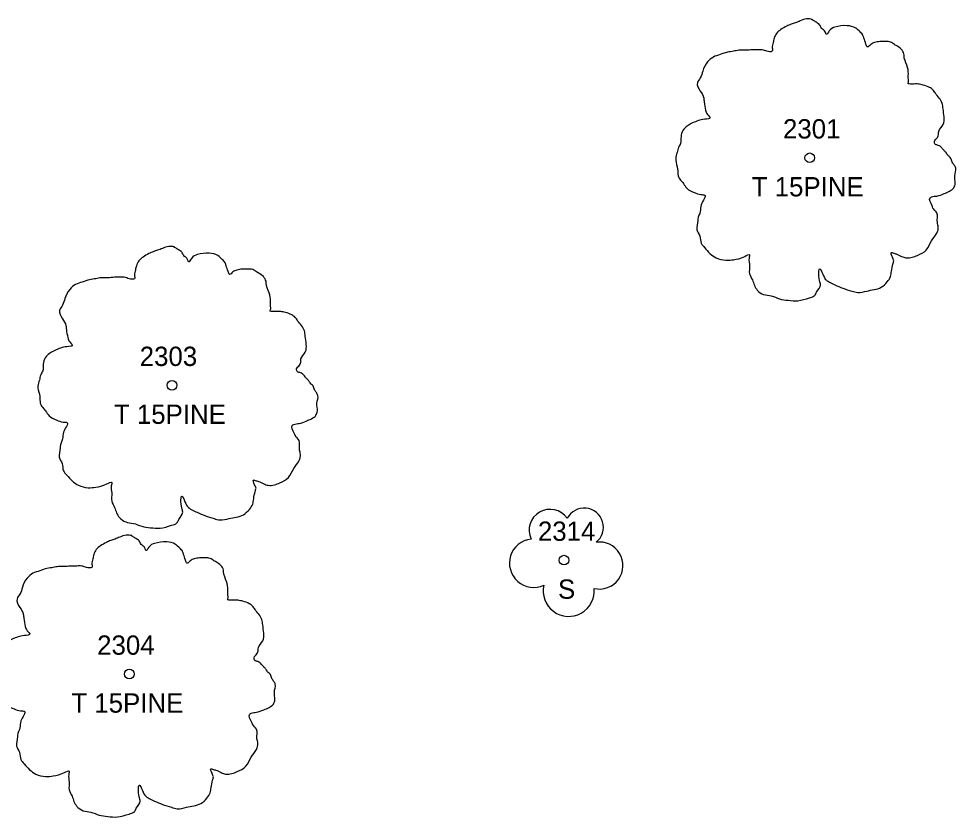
# Model space of a CAD drawing. Extents: x 2266664 to 2272542, y 716533 to 724777.
# Drawn here: x 2271573.66 to 2271622.19, y 723538.94 to 723580.3 of the extents above; entities that cross this region are included whole.
import ezdxf

# ---------------------------------------------------------------- set-up
doc = ezdxf.new("R2010")
doc.units = 0
doc.layers.add('RD_EX_VEG', color=7, linetype='Continuous')
doc.layers.add('RD_EX_VEG_txCode', color=7, linetype='Continuous')

msp = doc.modelspace()

# ---------------------------------------------------------------- linework, layer by layer
at = {"layer": 'RD_EX_VEG'}
for centre, radius in [((2271614.608, 723573.096), 0.25), ((2271614.595, 723573.077), 0.0001), ((2271581.591, 723561.315), 0.25), ((2271581.579, 723561.296), 0.0001), ((2271601.883, 723552.26), 0.25), ((2271579.387, 723546.361), 0.25), ((2271579.375, 723546.342), 0.0001)]:
    msp.add_circle(centre, radius, dxfattribs=at)
for centre, radius, start, end in [((2271601.162, 723553.807), 1.084, 34.9763, 204.756), ((2271602.928, 723553.962), 0.995, 308.7626, 152.0467), ((2271600.319, 723552.105), 1.257, 96.4518, 294.734), ((2271603.722, 723551.981), 1.218, 256.5667, 98.1046), ((2271602.128, 723550.664), 1.318, 166.8827, 5.7589)]:
    msp.add_arc(centre, radius, start, end, dxfattribs=at)
for points in [[(2271614.74, 723580.263), (2271614.44, 723580.288), (2271614.115, 723580.188), (2271613.865, 723580.088), (2271613.64, 723580.013), (2271613.415, 723579.913), (2271613.115, 723579.738), (2271612.89, 723579.538), (2271612.765, 723579.288), (2271612.715, 723579.063), (2271612.666, 723578.789), (2271612.666, 723578.614), (2271612.541, 723578.589), (2271612.391, 723578.614), (2271612.141, 723578.689), (2271611.891, 723578.689), (2271611.641, 723578.689), (2271611.291, 723578.664), (2271610.941, 723578.664), (2271610.666, 723578.614), (2271610.342, 723578.564), (2271609.967, 723578.439), (2271609.617, 723578.314), (2271609.317, 723578.064), (2271609.067, 723577.589), (2271608.942, 723577.239), (2271608.792, 723576.989), (2271608.942, 723576.54), (2271609.117, 723576.19), (2271609.142, 723575.99), (2271609.217, 723575.565), (2271609.317, 723575.34), (2271609.442, 723575.14), (2271609.367, 723575.115), (2271608.992, 723575.065), (2271608.692, 723574.965), (2271608.267, 723574.74), (2271608.043, 723574.515), (2271607.943, 723574.191), (2271607.918, 723573.841), (2271607.818, 723573.641), (2271607.743, 723573.366), (2271607.718, 723573.291), (2271607.668, 723572.966), (2271607.768, 723572.516), (2271607.793, 723572.166), (2271607.918, 723571.942), (2271608.068, 723571.767), (2271608.242, 723571.517), (2271608.642, 723571.292), (2271608.967, 723571.192), (2271609.167, 723571.167), (2271608.992, 723570.667), (2271608.942, 723570.317), (2271608.817, 723569.917), (2271608.817, 723569.843), (2271608.767, 723569.368), (2271608.917, 723569.043), (2271608.992, 723568.668), (2271609.167, 723568.443), (2271609.442, 723568.143), (2271609.767, 723567.918), (2271610.267, 723567.793), (2271610.666, 723567.818), (2271611.241, 723567.993), (2271611.491, 723568.068), (2271611.466, 723567.893), (2271611.491, 723567.518), (2271611.491, 723567.094), (2271611.641, 723566.769), (2271611.741, 723566.494), (2271611.891, 723566.244), (2271612.216, 723566.019), (2271612.616, 723565.944), (2271613.04, 723565.794), (2271613.49, 723565.719), (2271613.99, 723565.694), (2271614.59, 723565.844), (2271614.865, 723565.969), (2271614.965, 723566.144), (2271615.164, 723566.519), (2271615.114, 723566.744), (2271615.139, 723567.344), (2271615.239, 723567.169), (2271615.414, 723566.819), (2271615.914, 723566.519), (2271616.314, 723566.344), (2271616.789, 723566.194), (2271617.089, 723566.119), (2271617.563, 723566.194), (2271617.938, 723566.269), (2271618.313, 723566.394), (2271618.613, 723566.669), (2271618.788, 723566.944), (2271618.838, 723567.219), (2271618.913, 723567.593), (2271618.963, 723567.768)], [(2271618.963, 723567.768), (2271618.888, 723567.943), (2271618.838, 723568.193), (2271618.913, 723568.168), (2271619.088, 723568.118), (2271619.363, 723567.993), (2271619.588, 723567.918), (2271619.912, 723567.943), (2271620.187, 723568.043), (2271620.637, 723568.318), (2271620.912, 723568.793), (2271621.187, 723569.193), (2271621.262, 723569.518), (2271621.212, 723569.743), (2271621.187, 723570.242), (2271620.987, 723570.492), (2271620.937, 723570.617), (2271620.837, 723571.017), (2271620.912, 723571.067), (2271621.187, 723571.117), (2271621.562, 723571.242), (2271621.837, 723571.367), (2271622.061, 723571.542), (2271622.136, 723571.767), (2271622.111, 723572.166), (2271622.161, 723572.566), (2271622.086, 723572.716), (2271621.986, 723572.866), (2271621.911, 723573.066), (2271621.762, 723573.216), (2271621.662, 723573.366), (2271621.562, 723573.466), (2271621.437, 723573.616), (2271621.262, 723573.741), (2271621.112, 723573.791), (2271621.062, 723573.941), (2271621.212, 723574.141), (2271621.262, 723574.241), (2271621.287, 723574.465), (2271621.512, 723574.815), (2271621.562, 723575.215), (2271621.512, 723575.64), (2271621.462, 723575.915), (2271621.312, 723576.19), (2271621.112, 723576.44), (2271620.987, 723576.615), (2271620.812, 723576.739), (2271620.487, 723576.864), (2271620.237, 723576.914), (2271619.887, 723576.914), (2271619.687, 723576.964), (2271619.712, 723577.014), (2271619.712, 723577.164), (2271619.712, 723577.439), (2271619.637, 723577.889), (2271619.488, 723578.389), (2271619.488, 723578.414), (2271619.388, 723578.664), (2271619.163, 723578.864), (2271618.988, 723578.963), (2271618.788, 723579.088), (2271618.538, 723579.113), (2271618.238, 723579.113), (2271617.963, 723579.063), (2271617.763, 723578.963), (2271617.588, 723578.839), (2271617.513, 723578.988), (2271617.413, 723579.288), (2271617.363, 723579.438), (2271617.214, 723579.613), (2271616.989, 723579.813), (2271616.539, 723579.938), (2271615.914, 723579.863), (2271615.614, 723579.663), (2271615.464, 723579.488), (2271615.414, 723579.613), (2271615.214, 723579.813), (2271615.114, 723579.988), (2271614.94, 723580.113), (2271614.79, 723580.213), (2271614.69, 723580.263)], [(2271581.723, 723568.482), (2271581.423, 723568.507), (2271581.099, 723568.407), (2271580.849, 723568.308), (2271580.624, 723568.233), (2271580.399, 723568.133), (2271580.099, 723567.958), (2271579.874, 723567.758), (2271579.749, 723567.508), (2271579.699, 723567.283), (2271579.649, 723567.008), (2271579.649, 723566.833), (2271579.524, 723566.808), (2271579.374, 723566.833), (2271579.124, 723566.908), (2271578.874, 723566.908), (2271578.625, 723566.908), (2271578.275, 723566.883), (2271577.925, 723566.883), (2271577.65, 723566.833), (2271577.325, 723566.783), (2271576.95, 723566.658), (2271576.6, 723566.533), (2271576.301, 723566.283), (2271576.051, 723565.809), (2271575.926, 723565.459), (2271575.776, 723565.209), (2271575.926, 723564.759), (2271576.101, 723564.409), (2271576.126, 723564.209), (2271576.201, 723563.785), (2271576.301, 723563.56), (2271576.426, 723563.36), (2271576.351, 723563.335), (2271575.976, 723563.285), (2271575.676, 723563.185), (2271575.251, 723562.96), (2271575.026, 723562.735), (2271574.926, 723562.41), (2271574.901, 723562.06), (2271574.801, 723561.86), (2271574.726, 723561.585), (2271574.701, 723561.51), (2271574.651, 723561.186), (2271574.751, 723560.736), (2271574.776, 723560.386), (2271574.901, 723560.161), (2271575.051, 723559.986), (2271575.226, 723559.736), (2271575.626, 723559.511), (2271575.951, 723559.411), (2271576.151, 723559.386), (2271575.976, 723558.887), (2271575.926, 723558.537), (2271575.801, 723558.137), (2271575.801, 723558.062), (2271575.751, 723557.587), (2271575.901, 723557.262), (2271575.976, 723556.888), (2271576.151, 723556.663), (2271576.426, 723556.363), (2271576.75, 723556.138), (2271577.25, 723556.013), (2271577.65, 723556.038), (2271578.225, 723556.213), (2271578.475, 723556.288), (2271578.45, 723556.113), (2271578.475, 723555.738), (2271578.475, 723555.313), (2271578.625, 723554.988), (2271578.725, 723554.713), (2271578.874, 723554.464), (2271579.199, 723554.239), (2271579.599, 723554.164), (2271580.024, 723554.014), (2271580.474, 723553.939), (2271580.974, 723553.914), (2271581.573, 723554.064), (2271581.848, 723554.189), (2271581.948, 723554.364), (2271582.148, 723554.738), (2271582.098, 723554.963), (2271582.123, 723555.563), (2271582.223, 723555.388), (2271582.398, 723555.038), (2271582.898, 723554.738), (2271583.298, 723554.564), (2271583.772, 723554.414), (2271584.072, 723554.339), (2271584.547, 723554.414), (2271584.922, 723554.489), (2271585.297, 723554.614), (2271585.597, 723554.888), (2271585.771, 723555.163), (2271585.821, 723555.438), (2271585.896, 723555.813), (2271585.946, 723555.988)], [(2271585.946, 723555.988), (2271585.871, 723556.163), (2271585.821, 723556.413), (2271585.896, 723556.388), (2271586.071, 723556.338), (2271586.346, 723556.213), (2271586.571, 723556.138), (2271586.896, 723556.163), (2271587.171, 723556.263), (2271587.621, 723556.538), (2271587.896, 723557.012), (2271588.17, 723557.412), (2271588.245, 723557.737), (2271588.195, 723557.962), (2271588.17, 723558.462), (2271587.97, 723558.712), (2271587.92, 723558.837), (2271587.821, 723559.236), (2271587.896, 723559.286), (2271588.17, 723559.336), (2271588.545, 723559.461), (2271588.82, 723559.586), (2271589.045, 723559.761), (2271589.12, 723559.986), (2271589.095, 723560.386), (2271589.145, 723560.786), (2271589.07, 723560.936), (2271588.97, 723561.086), (2271588.895, 723561.286), (2271588.745, 723561.435), (2271588.645, 723561.585), (2271588.545, 723561.685), (2271588.42, 723561.835), (2271588.245, 723561.96), (2271588.095, 723562.01), (2271588.045, 723562.16), (2271588.195, 723562.36), (2271588.245, 723562.46), (2271588.27, 723562.685), (2271588.495, 723563.035), (2271588.545, 723563.435), (2271588.495, 723563.859), (2271588.445, 723564.134), (2271588.295, 723564.409), (2271588.095, 723564.659), (2271587.97, 723564.834), (2271587.796, 723564.959), (2271587.471, 723565.084), (2271587.221, 723565.134), (2271586.871, 723565.134), (2271586.671, 723565.184), (2271586.696, 723565.234), (2271586.696, 723565.384), (2271586.696, 723565.659), (2271586.621, 723566.108), (2271586.471, 723566.608), (2271586.471, 723566.633), (2271586.371, 723566.883), (2271586.146, 723567.083), (2271585.971, 723567.183), (2271585.771, 723567.308), (2271585.522, 723567.333), (2271585.222, 723567.333), (2271584.947, 723567.283), (2271584.747, 723567.183), (2271584.572, 723567.058), (2271584.497, 723567.208), (2271584.397, 723567.508), (2271584.347, 723567.658), (2271584.197, 723567.833), (2271583.972, 723568.033), (2271583.522, 723568.158), (2271582.898, 723568.083), (2271582.598, 723567.883), (2271582.448, 723567.708), (2271582.398, 723567.833), (2271582.198, 723568.033), (2271582.098, 723568.208), (2271581.923, 723568.333), (2271581.773, 723568.432), (2271581.673, 723568.482)], [(2271579.519, 723553.528), (2271579.219, 723553.553), (2271578.894, 723553.453), (2271578.644, 723553.353), (2271578.42, 723553.278), (2271578.195, 723553.178), (2271577.895, 723553.003), (2271577.67, 723552.803), (2271577.545, 723552.553), (2271577.495, 723552.328), (2271577.445, 723552.054), (2271577.445, 723551.879), (2271577.32, 723551.854), (2271577.17, 723551.879), (2271576.92, 723551.954), (2271576.67, 723551.954), (2271576.42, 723551.954), (2271576.071, 723551.929), (2271575.721, 723551.929), (2271575.446, 723551.879), (2271575.121, 723551.829), (2271574.746, 723551.704), (2271574.396, 723551.579), (2271574.096, 723551.329), (2271573.847, 723550.854), (2271573.722, 723550.504), (2271573.572, 723550.254), (2271573.722, 723549.805), (2271573.897, 723549.455), (2271573.921, 723549.255), (2271573.996, 723548.83), (2271574.096, 723548.605), (2271574.221, 723548.405), (2271574.146, 723548.38), (2271573.772, 723548.33), (2271573.472, 723548.23), (2271573.047, 723548.005), (2271572.822, 723547.78), (2271572.722, 723547.455), (2271572.697, 723547.106), (2271572.597, 723546.906), (2271572.522, 723546.631), (2271572.497, 723546.556), (2271572.447, 723546.231), (2271572.547, 723545.781), (2271572.572, 723545.431), (2271572.697, 723545.206), (2271572.847, 723545.032), (2271573.022, 723544.782), (2271573.422, 723544.557), (2271573.747, 723544.457), (2271573.946, 723544.432), (2271573.772, 723543.932), (2271573.722, 723543.582), (2271573.597, 723543.182), (2271573.597, 723543.107), (2271573.547, 723542.633), (2271573.697, 723542.308), (2271573.772, 723541.933), (2271573.946, 723541.708), (2271574.221, 723541.408), (2271574.546, 723541.183), (2271575.046, 723541.058), (2271575.446, 723541.083), (2271576.021, 723541.258), (2271576.27, 723541.333), (2271576.245, 723541.158), (2271576.27, 723540.783), (2271576.27, 723540.359), (2271576.42, 723540.034), (2271576.52, 723539.759), (2271576.67, 723539.509), (2271576.995, 723539.284), (2271577.395, 723539.209), (2271577.82, 723539.059), (2271578.27, 723538.984), (2271578.769, 723538.959), (2271579.369, 723539.109), (2271579.644, 723539.234), (2271579.744, 723539.409), (2271579.944, 723539.784), (2271579.894, 723540.009), (2271579.919, 723540.609), (2271580.019, 723540.434), (2271580.194, 723540.084), (2271580.694, 723539.784), (2271581.093, 723539.609), (2271581.568, 723539.459), (2271581.868, 723539.384), (2271582.343, 723539.459), (2271582.718, 723539.534), (2271583.092, 723539.659), (2271583.392, 723539.934), (2271583.567, 723540.209), (2271583.617, 723540.484), (2271583.692, 723540.858), (2271583.742, 723541.033)], [(2271583.742, 723541.033), (2271583.667, 723541.208), (2271583.617, 723541.458), (2271583.692, 723541.433), (2271583.867, 723541.383), (2271584.142, 723541.258), (2271584.367, 723541.183), (2271584.692, 723541.208), (2271584.967, 723541.308), (2271585.416, 723541.583), (2271585.691, 723542.058), (2271585.966, 723542.458), (2271586.041, 723542.783), (2271585.991, 723543.007), (2271585.966, 723543.507), (2271585.766, 723543.757), (2271585.716, 723543.882), (2271585.616, 723544.282), (2271585.691, 723544.332), (2271585.966, 723544.382), (2271586.341, 723544.507), (2271586.616, 723544.632), (2271586.841, 723544.807), (2271586.916, 723545.032), (2271586.891, 723545.431), (2271586.941, 723545.831), (2271586.866, 723545.981), (2271586.766, 723546.131), (2271586.691, 723546.331), (2271586.541, 723546.481), (2271586.441, 723546.631), (2271586.341, 723546.731), (2271586.216, 723546.881), (2271586.041, 723547.006), (2271585.891, 723547.056), (2271585.841, 723547.206), (2271585.991, 723547.406), (2271586.041, 723547.505), (2271586.066, 723547.73), (2271586.291, 723548.08), (2271586.341, 723548.48), (2271586.291, 723548.905), (2271586.241, 723549.18), (2271586.091, 723549.455), (2271585.891, 723549.705), (2271585.766, 723549.879), (2271585.591, 723550.004), (2271585.267, 723550.129), (2271585.017, 723550.179), (2271584.667, 723550.179), (2271584.467, 723550.229), (2271584.492, 723550.279), (2271584.492, 723550.429), (2271584.492, 723550.704), (2271584.417, 723551.154), (2271584.267, 723551.654), (2271584.267, 723551.679), (2271584.167, 723551.929), (2271583.942, 723552.128), (2271583.767, 723552.228), (2271583.567, 723552.353), (2271583.317, 723552.378), (2271583.018, 723552.378), (2271582.743, 723552.328), (2271582.543, 723552.228), (2271582.368, 723552.103), (2271582.293, 723552.253), (2271582.193, 723552.553), (2271582.143, 723552.703), (2271581.993, 723552.878), (2271581.768, 723553.078), (2271581.318, 723553.203), (2271580.694, 723553.128), (2271580.394, 723552.928), (2271580.244, 723552.753), (2271580.194, 723552.878), (2271579.994, 723553.078), (2271579.894, 723553.253), (2271579.719, 723553.378), (2271579.569, 723553.478), (2271579.469, 723553.528)]]:
    msp.add_spline(points, degree=3, dxfattribs=at)

# ---------------------------------------------------------------- texts
at = {"layer": 'RD_EX_VEG_txCode'}
for s, p in [('2301', (2271613.222, 723574.096)), ('T 15PINE', (2271611.604, 723571.096)), ('2303', (2271579.922, 723562.315)), ('T 15PINE', (2271578.587, 723559.315)), ('2314', (2271600.536, 723553.26)), ('S', (2271601.576, 723550.26)), ('2304', (2271577.718, 723547.361)), ('T 15PINE', (2271576.383, 723544.361))]:
    msp.add_text(s, height=1, dxfattribs=at).set_placement(p)

doc.saveas('drawing.dxf')
